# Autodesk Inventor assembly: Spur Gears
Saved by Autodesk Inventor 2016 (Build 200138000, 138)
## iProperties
Created: 2015-03
Part Number: Spur Gears
Document SubType Name: Assembly
Designer: Uglješa
Categories: <?xml version="1.0" encoding="UTF-16"?> <MemberInstance><Categories><FamilyTemplate/><ParamToTemplateMap><ParamToTemplate><ParamToTemplate CategoryParameter="//
Mass: 1547.82 g
Surface Area: 438.622 cm^2
Volume: 197.174 cm^3
Density: 7.85 g/cm^3
ClientObjectVersion: 1
Author: Uglješa
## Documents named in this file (3)
- C:\Users\Ugljesa\Desktop\Turbokompr\Assembly1\Design Accelerator\Spur Gears1.iam
- C:\Users\Ugljesa\Desktop\Turbokompr\Assembly1\Design Accelerator\Spur Gear21.ipt
- C:\Users\Ugljesa\Desktop\Turbokompr\Assembly1\Design Accelerator\44880B5DDE5B4817B2976B6FD3E330F7.ipt
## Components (2 placed, 2 different names)
1. Spur Gear2:1 — Rotation:1
2. 44880B5DDE5B4817B2976B6FD3E330F7:1 — Rotation:1
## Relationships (1: RelateRotation 1)
- Rotation:1 [RelateRotation]: Spur Gear2:1 ↔ 44880B5DDE5B4817B2976B6FD3E330F7:1
